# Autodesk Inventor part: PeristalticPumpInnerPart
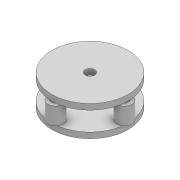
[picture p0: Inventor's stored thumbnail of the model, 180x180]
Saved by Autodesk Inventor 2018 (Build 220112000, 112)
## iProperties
Created: 2018-02
Part Number: PeristalticPumpInnerPart
Material: Generic
Document SubType Name: Modeling
Designer: arivu
Density: 1 g/cm^3
Appearance: Default
Author: arivu
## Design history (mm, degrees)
sketch "Sketch1"
  geometry: C1 r 20 at (0, 0); C2 r 2 at (0, 18); C3 r 2 at (18, 0); C4 r 2 at (0, -18); C5 r 2 at (-18, 0); 1 further point
  constraints: 5 centre point, 1 coincident, 9 other
  dimensions: "d0" = 40 diameter of C1; "d3" = 360 deg dimension on point (0, 0) C2.centre (derived)
extrude "Extrusion1" new body sketch "Sketch1" distance "d5" = 3; taper "d6" = 0 deg
sketch "Sketch2"
  geometry: C1 r 2 at (0, 18); 1 further point
  constraints: 1 centre point
extrude "Extrusion2" join sketch "Sketch2" distance "d7" = 10; taper "d8" = 0 deg
pattern_circular "Circular Pattern1" dims angle "d10" = 360 deg
workplane "Work Plane1"
sketch "Sketch5"
  geometry: C1 r 2.2 at (0, 0); C2 r 4 at (0, 0); 1 further point
  constraints: 2 centre point, 1 coincident
  dimensions: "d13" = 4.4 diameter of C1; "d14" = 8 diameter of C2
extrude "Extrusion3" join sketch "Sketch5" distance "d15" = 9; taper "d16" = 0 deg
pattern_circular "Circular Pattern2" dims angle "d18" = 360 deg
sketch "Sketch6"
  geometry: C1 r 20 at (0, -18); 1 further point
  constraints: 1 centre point, 1 coincident
extrude "Extrusion4" join sketch "Sketch6" distance "d20" = 3; taper "d21" = 0 deg
sketch "Sketch7"
  geometry: C1 r 2.5 at (0, 0); 1 further point
  constraints: 1 centre point, 1 coincident
  dimensions: "d22" = 5 diameter of C1
extrude "Extrusion5" cut sketch "Sketch7" distance "d23" = 16; taper "d24" = 0 deg
body "Solid1"
other parameters: "d12" = 0.5
